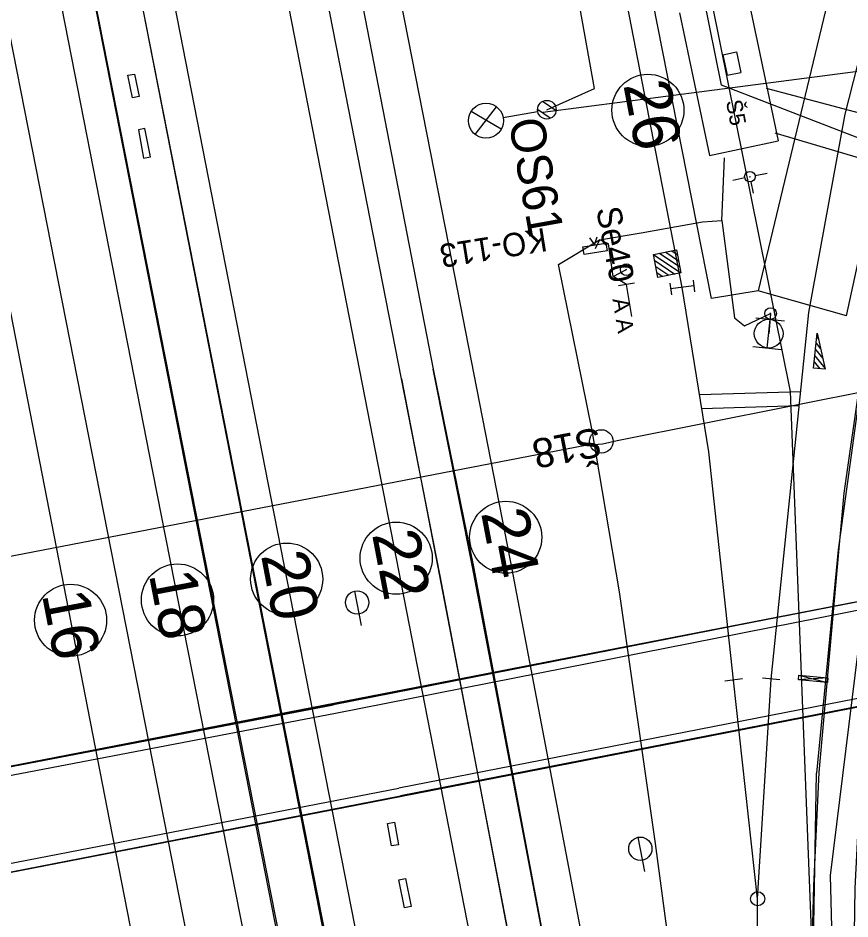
# Model space of a CAD drawing. Extents: x -545736 to -544888, y -1122892 to -1119128.
# Drawn here: x -545134.33 to -545098.74, y -1121893.1 to -1121854.55 of the extents above; entities that cross this region are included whole.
import ezdxf

# ---------------------------------------------------------------- set-up
doc = ezdxf.new("R2010")
doc.units = 0
for name, color, linetype in [('osvětlené plochy-hodnota-obrys', 7, 'Continuous'), ('Vrstva 1', 7, 'Continuous'), ('Vrstva 16', 7, 'Continuous'), ('Vrstva 2', 7, 'Continuous'), ('Vrstva 23', 7, 'Continuous'), ('Vrstva 25', 7, 'Continuous'), ('Vrstva 26', 7, 'Continuous'), ('Vrstva 27', 7, 'Continuous'), ('Vrstva 28 - zabzar', 7, 'Continuous'), ('Vrstva 3', 7, 'Continuous'), ('Vrstva 3 - Lisy - Pocitaci body', 7, 'Continuous'), ('Vrstva 35', 7, 'Continuous'), ('Vrstva 36', 7, 'Continuous'), ('Vrstva 41', 7, 'Continuous'), ('Vrstva 43', 7, 'Continuous'), ('Vrstva 44', 7, 'Continuous'), ('Vrstva 49', 7, 'Continuous'), ('Vrstva 6 - Navesti', 7, 'Continuous'), ('Vrstva 61', 7, 'Continuous'), ('Vrstva 63', 7, 'Continuous'), ('Vrstva 7 - Namezniky-vystroj', 7, 'Continuous')]:
    doc.layers.add(name, color=color, linetype=linetype)

msp = doc.modelspace()

# ---------------------------------------------------------------- linework, layer by layer
at = {"layer": 'osvětlené plochy-hodnota-obrys'}
for points in [[(-545114.36, -1122142.005), (-545095.834, -1122030.811), (-545094.039, -1122008.497), (-545094.672, -1121983.393), (-545097.737, -1121961.902), (-545099.42, -1121918.553), (-545101.285, -1121870.536), (-545123.71, -1121759.379), (-545130.296, -1121736.567), (-545147.419, -1121693.847), (-545162.352, -1121662.092), (-545176.655, -1121642.604), (-545199.404, -1121614.631), (-545212.209, -1121594.037), (-545225.557, -1121565.516)], [(-545115.194, -1122188.84), (-545115.464, -1122158.52), (-545110.116, -1122078.531), (-545109.516, -1122044.98), (-545111.654, -1121993.485), (-545115.876, -1121955.778), (-545121.955, -1121920.051), (-545160.528, -1121723.806), (-545171.589, -1121690.909), (-545189.933, -1121650.816), (-545214.916, -1121599.46)]]:
    msp.add_lwpolyline(points, dxfattribs=at)
at = {"layer": 'Vrstva 1'}
msp.add_line((-545102.693, -1121892.238), (-545102.113, -1121882.835), dxfattribs=at)
for points in [[(-545109.452, -1121897.864), (-545113.266, -1121877.758), (-545115.89, -1121864.333), (-545119.706, -1121844.859), (-545122.391, -1121831.073)], [(-545102.771, -1121915.018), (-545102.732, -1121903.684), (-545102.71, -1121897.208), (-545102.693, -1121892.238), (-545103.72, -1121882.881), (-545104.775, -1121873.115), (-545105.919, -1121866.08), (-545109.311, -1121848.591), (-545112.214, -1121833.922)], [(-545102.113, -1121882.835), (-545100.504, -1121867.161), (-545098.949, -1121858.665), (-545095.447, -1121844.904), (-545093.58, -1121839.064)], [(-545103.4, -1121953.3), (-545106.937, -1121935.184), (-545112.444, -1121906.934), (-545125.527, -1121839.782)], [(-545113.887, -1121998.538), (-545114.726, -1121986.367), (-545115.084, -1121982.113), (-545116.437, -1121968.628), (-545118.368, -1121953.708), (-545121.658, -1121933.786), (-545126, -1121911.447), (-545130.401, -1121888.923), (-545134.741, -1121866.64), (-545139.463, -1121842.499)], [(-545134.071, -1121845.897), (-545128.577, -1121873.956), (-545119.95, -1121917.752), (-545116.436, -1121936.376), (-545113.726, -1121953.511), (-545111.671, -1121970.139), (-545110.636, -1121980.411)], [(-545110.223, -1121943.326), (-545119.802, -1121894.017), (-545123.633, -1121874.443), (-545127.995, -1121852.099)]]:
    msp.add_lwpolyline(points, dxfattribs=at)
for centre in [(-545107.389, -1121858.501), (-545113.472, -1121876.77), (-545118.158, -1121877.664), (-545122.842, -1121878.558), (-545127.513, -1121879.45), (-545132.086, -1121880.322)]:
    msp.add_circle(centre, 1.542, dxfattribs=at)
at = {"layer": 'Vrstva 16'}
for p, q in [((-545117.924, -1121869.987), (-545124.972, -1121833.972)), ((-545133.943, -1121839.088), (-545122.459, -1121897.438)), ((-545122.517, -1121897.456), (-545133.943, -1121839.088)), ((-545131.48, -1121841.454), (-545120.814, -1121896.01)), ((-545120.748, -1121896.001), (-545131.48, -1121841.454)), ((-545098.898, -1121867.298), (-545097.703, -1121861.777))]:
    msp.add_line(p, q, dxfattribs=at)
for points in [[(-545124.972, -1121833.972), (-545123.527, -1121833.704), (-545116.576, -1121869.582)], [(-545107.528, -1121836.133), (-545104.785, -1121849.79), (-545098.835, -1121850.244), (-545102.676, -1121866.22)], [(-545098.898, -1121867.298), (-545102.676, -1121866.22), (-545104.669, -1121866.55), (-545107.591, -1121851.721), (-545110.484, -1121836.846)]]:
    msp.add_lwpolyline(points, dxfattribs=at)
for points in [[(-545111.707, -1121894.707), (-545114.886, -1121878.034), (-545116.576, -1121869.582), (-545114.855, -1121878.031)], [(-545113.118, -1121894.979), (-545116.273, -1121878.422), (-545117.924, -1121869.987), (-545116.299, -1121878.421)]]:
    msp.add_lwpolyline(points, close=True, dxfattribs=at)
at = {"layer": 'Vrstva 2'}
for p, q in [((-545103.348, -1121882.832), (-545104.092, -1121882.93)), ((-545101.74, -1121882.873), (-545102.486, -1121882.797))]:
    msp.add_line(p, q, dxfattribs=at)
for points in [[(-545102.732, -1121903.684), (-545102.71, -1121897.208), (-545102.693, -1121892.238), (-545103.72, -1121882.881)], [(-545102.71, -1121897.208), (-545102.693, -1121892.238), (-545102.113, -1121882.835)]]:
    msp.add_lwpolyline(points, dxfattribs=at)
msp.add_circle((-545102.693, -1121892.238), 0.3, dxfattribs=at)
at = {"layer": 'Vrstva 23'}
for p, q in [((-545143.668, -1121888.303), (-545092.208, -1121878.305)), ((-545092.219, -1121878.316), (-545120.835, -1121883.939)), ((-545120.759, -1121884.295), (-545092.216, -1121878.665)), ((-545120.851, -1121883.909), (-545143.623, -1121888.305)), ((-545143.607, -1121888.299), (-545120.835, -1121883.939)), ((-545143.526, -1121888.664), (-545120.759, -1121884.295)), ((-545142.795, -1121892.29), (-545118.037, -1121887.503)), ((-545142.746, -1121892.665), (-545117.967, -1121887.839)), ((-545142.78, -1121892.682), (-545119.878, -1121888.237))]:
    msp.add_line(p, q, dxfattribs=at)
for points in [[(-545091.758, -1121878.218), (-545096.276, -1121879.121), (-545120.851, -1121883.909)], [(-545119.878, -1121888.237), (-545095.406, -1121883.444), (-545092.628, -1121883.665), (-545092.578, -1121883.394), (-545092.252, -1121883.397), (-545092.056, -1121881.717), (-545092.44, -1121881.752), (-545092.418, -1121881.159), (-545091.396, -1121881.243)], [(-545092.603, -1121883.309), (-545095.411, -1121883.091), (-545118.037, -1121887.503)], [(-545092.617, -1121883.654), (-545095.398, -1121883.427), (-545117.967, -1121887.839)]]:
    msp.add_lwpolyline(points, dxfattribs=at)
at = {"layer": 'Vrstva 25'}
for p, q in [((-545114.781, -1121859.532), (-545113.862, -1121858.356)), ((-545111.32, -1121858.529), (-545111.9, -1121858.126)), ((-545113.671, -1121859.316), (-545114.949, -1121858.547)), ((-545113.582, -1121858.814), (-545112.106, -1121858.548)), ((-545111.564, -1121858.846), (-545112.109, -1121858.467))]:
    msp.add_line(p, q, dxfattribs=at)
for centre, radius in [((-545114.318, -1121858.949), 0.749), ((-545111.712, -1121858.477), 0.4), ((-545111.712, -1121858.477), 0.4)]:
    msp.add_circle(centre, radius, dxfattribs=at)
at = {"layer": 'Vrstva 26'}
for points in [[(-545097.437, -1122052.623), (-545072.287, -1122039.894), (-545085.621, -1122009.744), (-545089.841, -1121964.946), (-545095.239, -1121958.274), (-545095.745, -1121940.272), (-545098.424, -1121935.947), (-545099.088, -1121910.293), (-545099.581, -1121891.247), (-545095.82, -1121860.673), (-545104.239, -1121857.434), (-545113.591, -1121811.167), (-545113.924, -1121803.223), (-545124.359, -1121753.762), (-545132.104, -1121728.782), (-545141.308, -1121704.806), (-545150.282, -1121669.65), (-545151.919, -1121656.143), (-545151.404, -1121636.531), (-545180.167, -1121637.447), (-545212.798, -1121581.796), (-545235.977, -1121514.184), (-545242.54, -1121484.599), (-545257.211, -1121409.362)], [(-545111.712, -1121858.477), (-545109.668, -1121857.569), (-545112.9, -1121839.62), (-545112.626, -1121838.172), (-545113.115, -1121836.08), (-545113.96, -1121833.409), (-545116.212, -1121821.755), (-545116.359, -1121819.204), (-545117.683, -1121812.861), (-545118.163, -1121810.398), (-545118.986, -1121810.372), (-545121.163, -1121800.213), (-545124.063, -1121784.124), (-545125.785, -1121784.075)]]:
    msp.add_lwpolyline(points, dxfattribs=at)
at = {"layer": 'Vrstva 27'}
for p, q in [((-545110.17, -1121864.348), (-545110.167, -1121864.344)), ((-545108.306, -1121865.345), (-545108.314, -1121865.295)), ((-545102.143, -1121867.225), (-545102.137, -1121867.175))]:
    msp.add_line(p, q, dxfattribs=at)
msp.add_lwpolyline([(-545109.894, -1121863.963), (-545109.676, -1121864.265), (-545109.565, -1121863.91)], dxfattribs=at)
msp.add_lwpolyline([(-545110.17, -1121864.345), (-545109.183, -1121864.186), (-545109.13, -1121864.515), (-545110.117, -1121864.674)], close=True, dxfattribs=at)
for centre in [(-545108.31, -1121865.32), (-545102.14, -1121867.2)]:
    msp.add_circle(centre, 0.25, dxfattribs=at)
at = {"layer": 'Vrstva 28 - zabzar'}
for points in [[(-545105.12, -1121903.09), (-545105.84, -1121899.05), (-545107.07, -1121889.87), (-545108.6, -1121879.1), (-545109.78, -1121872.2), (-545111.21, -1121865.1), (-545109.46, -1121864.04), (-545107.67, -1121863.75), (-545105.05, -1121863.27), (-545104.23, -1121863.22), (-545104.11, -1121860.53)], [(-545104.23, -1121863.22), (-545103.68, -1121867.38), (-545103.26, -1121867.72), (-545102.14, -1121867.2), (-545102.22, -1121868.06)], [(-545108.87, -1121865.61), (-545109.07, -1121864.22), (-545109.46, -1121864.04), (-545109.65, -1121864.43)], [(-545108.3, -1121865.96), (-545108.87, -1121865.61), (-545108.31, -1121865.32)]]:
    msp.add_lwpolyline(points, dxfattribs=at)
at = {"layer": 'Vrstva 3'}
for p, q in [((-545106.447, -1121865.897), (-545106.382, -1121866.393)), ((-545105.423, -1121866.015), (-545106.415, -1121866.145)), ((-545105.456, -1121865.767), (-545105.391, -1121866.263))]:
    msp.add_line(p, q, dxfattribs=at)
at = {"layer": 'Vrstva 3 - Lisy - Pocitaci body'}
for p, q in [((-545106.366, -1121864.518), (-545106.126, -1121864.68)), ((-545107.147, -1121864.67), (-545105.975, -1121865.461)), ((-545107.096, -1121864.93), (-545106.235, -1121865.511)), ((-545106.887, -1121864.619), (-545106.025, -1121865.201)), ((-545106.626, -1121864.569), (-545106.076, -1121864.94)), ((-545107.046, -1121865.19), (-545106.496, -1121865.562)), ((-545106.995, -1121865.45), (-545106.756, -1121865.612)), ((-545102.77, -1121867.384), (-545101.544, -1121867.51)), ((-545102.283, -1121868.673), (-545102.157, -1121867.447)), ((-545100.169, -1121868.209), (-545100.094, -1121868.302)), ((-545102.896, -1121868.61), (-545101.67, -1121868.736)), ((-545100.224, -1121868.736), (-545099.912, -1121869.12)), ((-545100.197, -1121868.473), (-545100.003, -1121868.711)), ((-545100.251, -1121869.001), (-545099.82, -1121869.529)), ((-545100.305, -1121869.528), (-545100.3, -1121869.534)), ((-545100.278, -1121869.264), (-545100.036, -1121869.561))]:
    msp.add_line(p, q, dxfattribs=at)
msp.add_lwpolyline([(-545106.165, -1121864.479), (-545105.975, -1121865.461), (-545106.957, -1121865.651), (-545107.147, -1121864.67)], close=True, dxfattribs=at)
msp.add_lwpolyline([(-545100.152, -1121868.041), (-545099.808, -1121869.584), (-545100.305, -1121869.533), (-545100.152, -1121868.041)], dxfattribs=at)
msp.add_circle((-545102.22, -1121868.057), 0.616, dxfattribs=at)
at = {"layer": 'Vrstva 35'}
for points in [[(-545094.766, -1121939.919), (-545097.515, -1121935.57), (-545098.514, -1121899.276), (-545098.598, -1121896.563), (-545098.524, -1121891.782), (-545098.28, -1121887.009), (-545097.43, -1121877.391), (-545097.227, -1121875.04), (-545095.278, -1121862.596), (-545097.055, -1121862.323), (-545098.236, -1121869.684), (-545098.293, -1121869.911), (-545099.003, -1121874.881), (-545099.214, -1121877.242), (-545100.072, -1121886.841), (-545100.302, -1121891.691), (-545100.433, -1121896.532), (-545100.323, -1121899.371), (-545099.288, -1121936.136), (-545096.606, -1121940.329)], [(-545109.46, -1121864.04), (-545107.67, -1121863.75), (-545105.05, -1121863.27), (-545104.23, -1121863.22)]]:
    msp.add_lwpolyline(points, dxfattribs=at)
at = {"layer": 'Vrstva 36'}
for points in [[(-545129.444, -1121857.971), (-545129.641, -1121856.996), (-545129.346, -1121856.955), (-545129.155, -1121857.908)], [(-545128.965, -1121860.547), (-545128.661, -1121860.496), (-545128.905, -1121859.286), (-545129.182, -1121859.336)], [(-545118.352, -1121889.972), (-545118.529, -1121889.018), (-545118.223, -1121888.965), (-545118.06, -1121889.927)], [(-545117.806, -1121892.623), (-545118.04, -1121891.423), (-545117.758, -1121891.364), (-545117.515, -1121892.573)]]:
    msp.add_lwpolyline(points, close=True, dxfattribs=at)
at = {"layer": 'Vrstva 41'}
for p, q in [((-545103.761, -1121861.486), (-545103.246, -1121861.384)), ((-545103.05, -1121861.346), (-545103, -1121861.336)), ((-545102.804, -1121861.298), (-545102.289, -1121861.196)), ((-545102.982, -1121861.562), (-545102.885, -1121862.052))]:
    msp.add_line(p, q, dxfattribs=at)
msp.add_circle((-545103.025, -1121861.341), 0.225, dxfattribs=at)
at = {"layer": 'Vrstva 43'}
for p, q in [((-545119.635, -1121880.545), (-545119.921, -1121879.074)), ((-545107.52, -1121891.078), (-545107.808, -1121889.608))]:
    msp.add_line(p, q, dxfattribs=at)
for centre, radius in [((-545109.381, -1121872.67), 0.5), ((-545119.826, -1121879.563), 0.498), ((-545107.712, -1121890.097), 0.498)]:
    msp.add_circle(centre, radius, dxfattribs=at)
at = {"layer": 'Vrstva 44'}
msp.add_lwpolyline([(-545094.826, -1121887.512), (-545094.254, -1121887.557), (-545092.865, -1121887.668), (-545091.72, -1121887.758), (-545090.268, -1121887.873), (-545086.549, -1121888.168), (-545079.866, -1121888.698), (-545079.307, -1121888.256), (-545078.235, -1121887.388), (-545078.119, -1121886.246), (-545076.573, -1121871.721), (-545077.268, -1121870.044), (-545079.088, -1121869.124), (-545086.504, -1121868.907), (-545093.818, -1121869.676), (-545108.699, -1121872.648), (-545109.324, -1121872.781), (-545110.052, -1121872.845), (-545138.969, -1121878.416), (-545139.513, -1121878.622), (-545139.779, -1121877.836), (-545147.175, -1121839.811)], dxfattribs=at)
at = {"layer": 'Vrstva 49'}
for p, q in [((-545103.103, -1121853.71), (-545101.816, -1121859.816)), ((-545106.039, -1121854.329), (-545104.752, -1121860.435)), ((-545104.179, -1121856.124), (-545103.592, -1121856)), ((-545103.592, -1121856), (-545103.406, -1121856.881)), ((-545104.179, -1121856.124), (-545103.993, -1121857.005)), ((-545103.993, -1121857.005), (-545103.406, -1121856.881)), ((-545097.295, -1121858.905), (-545102.311, -1121857.563)), ((-545097.557, -1121860.788), (-545101.938, -1121859.477)), ((-545104.752, -1121860.435), (-545101.816, -1121859.816))]:
    msp.add_line(p, q, dxfattribs=at)
for points in [[(-545097.144, -1121861.928), (-545099.25, -1121877.31), (-545100.173, -1121886.859)], [(-545087.235, -1122001.271), (-545090.316, -1121965.561), (-545096.113, -1121958.592), (-545096.577, -1121940.383), (-545099.261, -1121936.178), (-545100.352, -1121896.608), (-545100.173, -1121886.859)]]:
    msp.add_lwpolyline(points, dxfattribs=at)
at = {"layer": 'Vrstva 6 - Navesti'}
for p, q in [((-545107.955, -1121865.904), (-545108.645, -1121866.016)), ((-545108.078, -1121867.328), (-545108.3, -1121865.96))]:
    msp.add_line(p, q, dxfattribs=at)
at = {"layer": 'Vrstva 63'}
msp.add_line((-545091.159, -1121855.897), (-545111.881, -1121858.592), dxfattribs=at)
at = {"layer": 'Vrstva 7 - Namezniky-vystroj'}
for p, q in [((-545105.173, -1121870.665), (-545100.851, -1121870.537)), ((-545105.076, -1121871.262), (-545100.912, -1121871.139)), ((-545100.931, -1121882.666), (-545099.705, -1121882.982))]:
    msp.add_line(p, q, dxfattribs=at)
msp.add_lwpolyline([(-545099.686, -1121882.783), (-545100.95, -1121882.865), (-545100.931, -1121882.666), (-545099.686, -1121882.783), (-545099.705, -1121882.982), (-545100.95, -1121882.865)], dxfattribs=at)

# ---------------------------------------------------------------- texts
at = {"layer": 'Vrstva 1'}
for s, p in [('26', (-545108.445, -1121857.408)), ('24', (-545114.53, -1121875.722)), ('22', (-545119.194, -1121876.637)), ('20', (-545123.943, -1121877.54)), ('18', (-545128.74, -1121878.353)), ('16', (-545133.316, -1121879.212))]:
    msp.add_text(s, height=2, rotation=280.8048, dxfattribs=at).set_placement(p)
at = {"layer": 'Vrstva 25'}
msp.add_text('OS61', height=1.5, rotation=280.2076, dxfattribs=at).set_placement((-545113.354, -1121858.958))
at = {"layer": 'Vrstva 27'}
msp.add_text('KO-113', height=1, rotation=189.1152, dxfattribs=at).set_placement((-545111.799, -1121863.527))
at = {"layer": 'Vrstva 43'}
msp.add_text('Š18', height=1.25, rotation=190.9047, dxfattribs=at).set_placement((-545109.499, -1121872.056))
at = {"layer": 'Vrstva 6 - Navesti'}
for s, height, rotation, p in [('Se40', 1.05, 280.9763, (-545109.609, -1121862.725)), ('  A A ', 0.7, 279.2363, (-545108.991, -1121866.072))]:
    msp.add_text(s, height=height, rotation=rotation, dxfattribs=at).set_placement(p)
at = {"layer": 'Vrstva 61'}
msp.add_text('Š5', height=0.6806, rotation=281.0281, dxfattribs=at).set_placement((-545104.055, -1121858.117))

doc.saveas('drawing.dxf')
